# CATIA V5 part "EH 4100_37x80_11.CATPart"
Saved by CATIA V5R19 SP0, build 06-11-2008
Definition: EH 4100/37x80/11
Nomenclature: EH 4100/37x80/11
Description: PART--DESC
Material "Steel": density 7860 kg/m3, Young's modulus 2e+11 Pa, Poisson ratio 0.266, thermal expansion 1.17e-05 1/K
Bounding box of the stored display mesh (mm): x 101.75 to 138.25, y 91.754 to 128.246, z -45.3 to 55
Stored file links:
  G:\UTB\Kombinované\Bakalářská práce\Catia\FORMA\EH 4100_37x80_11.CATPart
  D:\Aplikace\CATIA\Nová složka\win_b64\startup\materials\Catalog.CATMaterial
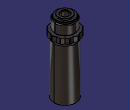
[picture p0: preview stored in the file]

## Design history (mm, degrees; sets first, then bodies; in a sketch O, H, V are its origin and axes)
Body1 "EH 4100/37x80/11" (main body)
  Solid1: solid without history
